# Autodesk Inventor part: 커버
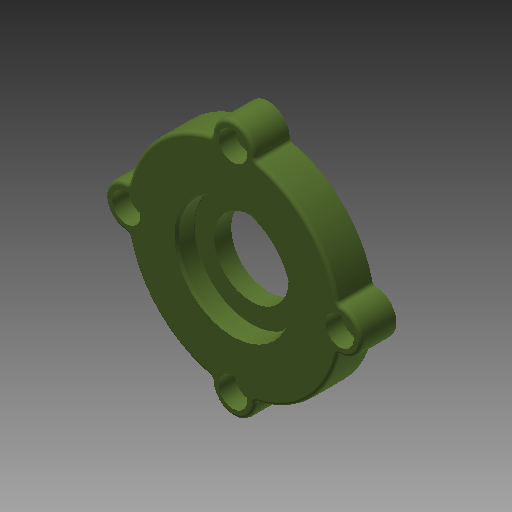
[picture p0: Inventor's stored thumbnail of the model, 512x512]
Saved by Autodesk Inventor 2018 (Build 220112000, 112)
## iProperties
Created: 2016-06
Part Number: 커버
Material: 알루미늄 6061
Document SubType Name: Modeling
Designer: mduedu
Density: 2.71 g/cm^3
Appearance: 올리브 녹색
Author: mduedu
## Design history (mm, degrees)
sketch "스케치1"
  geometry: C1 r 30 at (0, 0); 1 further point
  constraints: 1 centre point, 1 coincident
  dimensions: "d0" = 60 diameter of C1
extrude "돌출1" new body sketch "스케치1" distance "d2" = 10; taper "d3" = 0 deg
sketch "스케치5"
  geometry: C1 r 6 at (0, 30); 2 further points
  constraints: 2 vertical alignment, 1 centre point, 1 other
  dimensions: "d61" = 12 diameter of C1
extrude "돌출3" join sketch "스케치5" stored distance "d62" = 10; taper "d63" = 0 deg
sketch "스케치2"
  geometry: C1 r 21 at (0, 0); 1 further point
  constraints: 1 centre point, 1 coincident
  dimensions: "d4" = 42 diameter of C1
extrude "돌출2" join sketch "스케치2" distance "d6" = 3; taper "d7" = 0 deg
hole "구멍1" diameter "d11" = 35; stored, may be unused: countersink angle "d15" = 90 deg, drill point angle "d17" = 0 deg; dims "d9" = 10, "d10" = 10, "d12" = 6, "d13" = 4, "d14" = 2, "d16" = 3
hole "구멍2" diameter "d20" = 32; stored, may be unused: countersink angle "d24" = 90 deg, drill point angle "d26" = 0 deg; dims "d21" = 6, "d22" = 4, "d23" = 2, "d25" = 5.2, "d67" = 10, "d68" = 10
hole "구멍3" diameter "d29" = 21; stored, may be unused: countersink angle "d33" = 90 deg, drill point angle "d35" = 0 deg; dims "d27" = 10, "d28" = 10, "d30" = 6, "d31" = 4, "d32" = 2, "d34" = 5
fillet "모깎기2" dims "d36" = 3
fillet "모깎기3" dims "d37" = 0.1
chamfer "모따기1" distance "d38" = 0.75; stored, may be unused: second distance "d39" = 2, angle "d40" = 30 deg
chamfer "모따기2" distance "d42" = 0.5; stored, may be unused: second distance "d43" = 2, angle "d44" = 30 deg
sketch "스케치6"
  geometry: A1 r 30 centre (0, 0) between (29.4, 5.97) and (5.97, 29.4) reference; 3 further points
  constraints: 2 vertical alignment, 1 coincident, 3 other
hole "구멍5" sketch "스케치6" at (0, 30) diameter "d69" = 4.5; stored, may be unused: countersink angle "d73" = 90 deg, drill point angle "d75" = 118 deg; dims "d70" = 6, "d71" = 8, "d72" = 4.6, "d74" = 8
fillet "모깎기5" dims "d79" = 1
fillet "모깎기6" dims "d80" = 1
node "솔리드1"
pattern_circular "원형 패턴1" dims angle "d65" = 360 deg
pattern_circular "원형 패턴2" dims angle "d77" = 360 deg
node "투영된 루프1"
